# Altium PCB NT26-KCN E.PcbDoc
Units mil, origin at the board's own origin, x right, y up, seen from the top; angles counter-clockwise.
Board outline 1222.67 x 1229.6 mil, 4 copper layers (Top Layer, GND1, Signal Layer 1, Bottom Layer), stack 29.559 mil thick; 1 components, 0 nets, 109 pads, 0 vias.
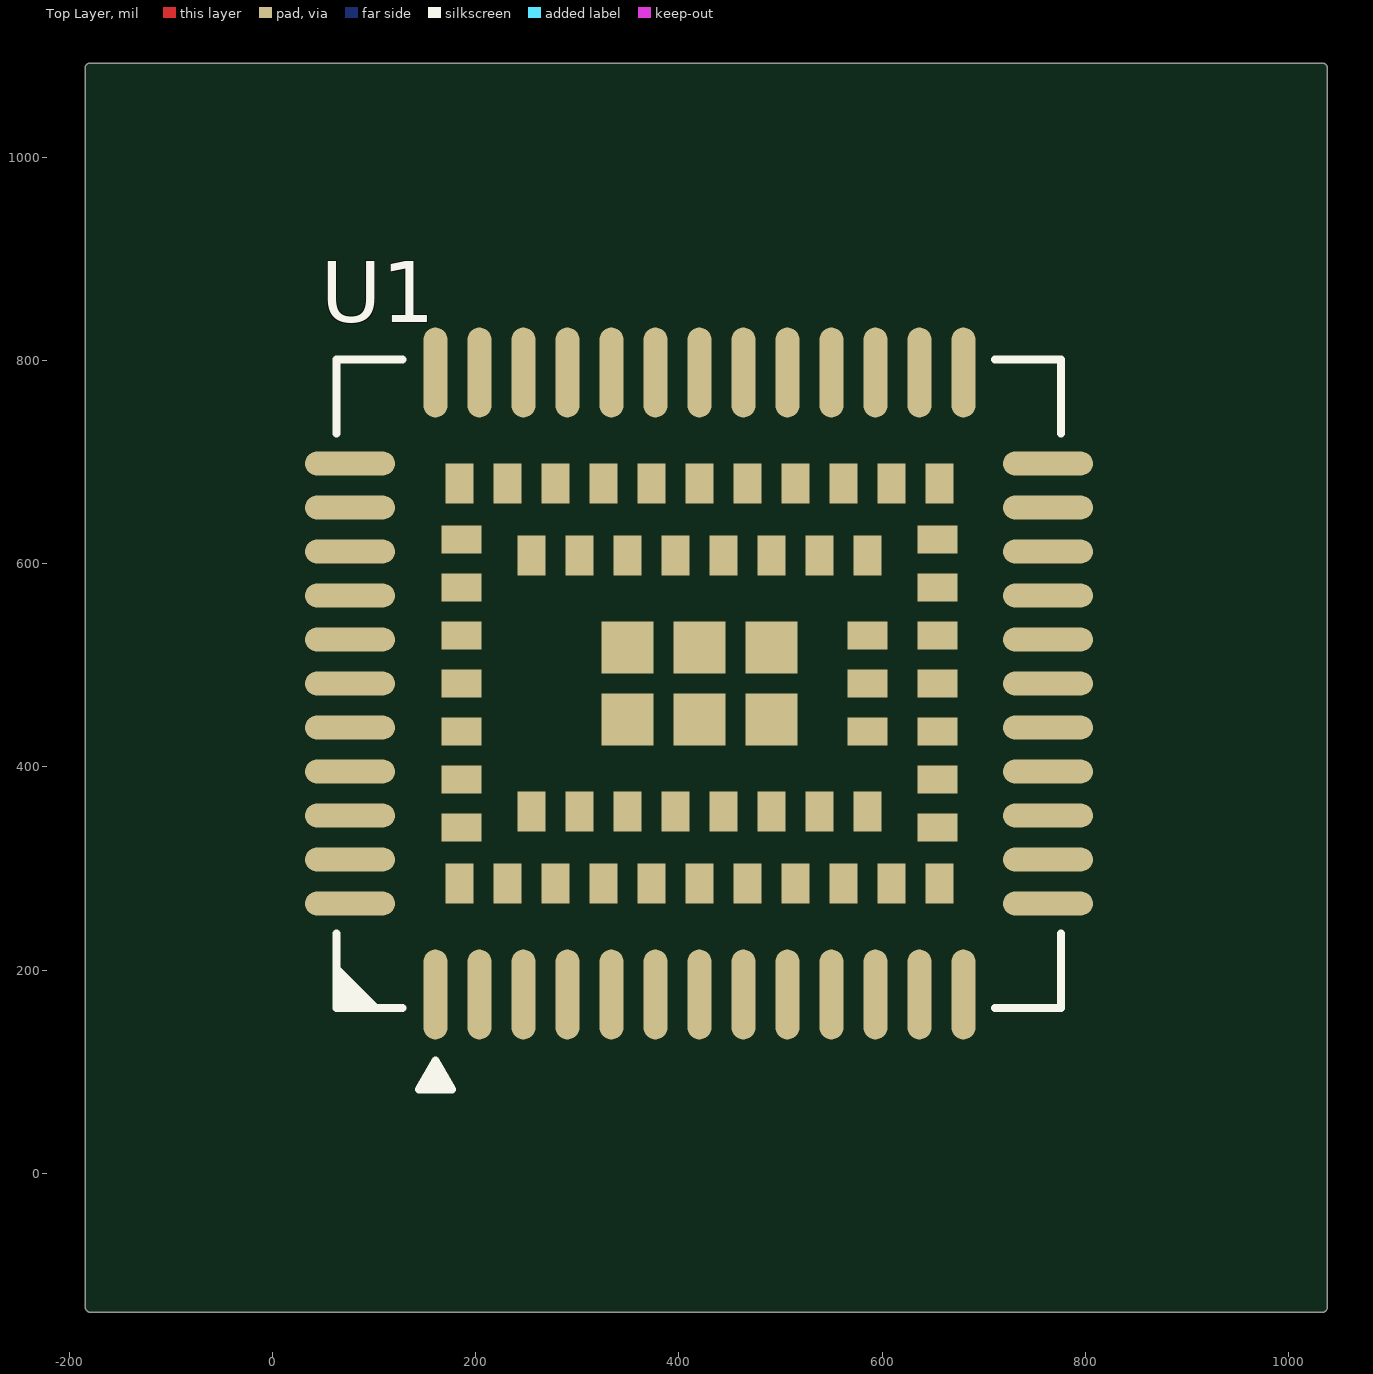
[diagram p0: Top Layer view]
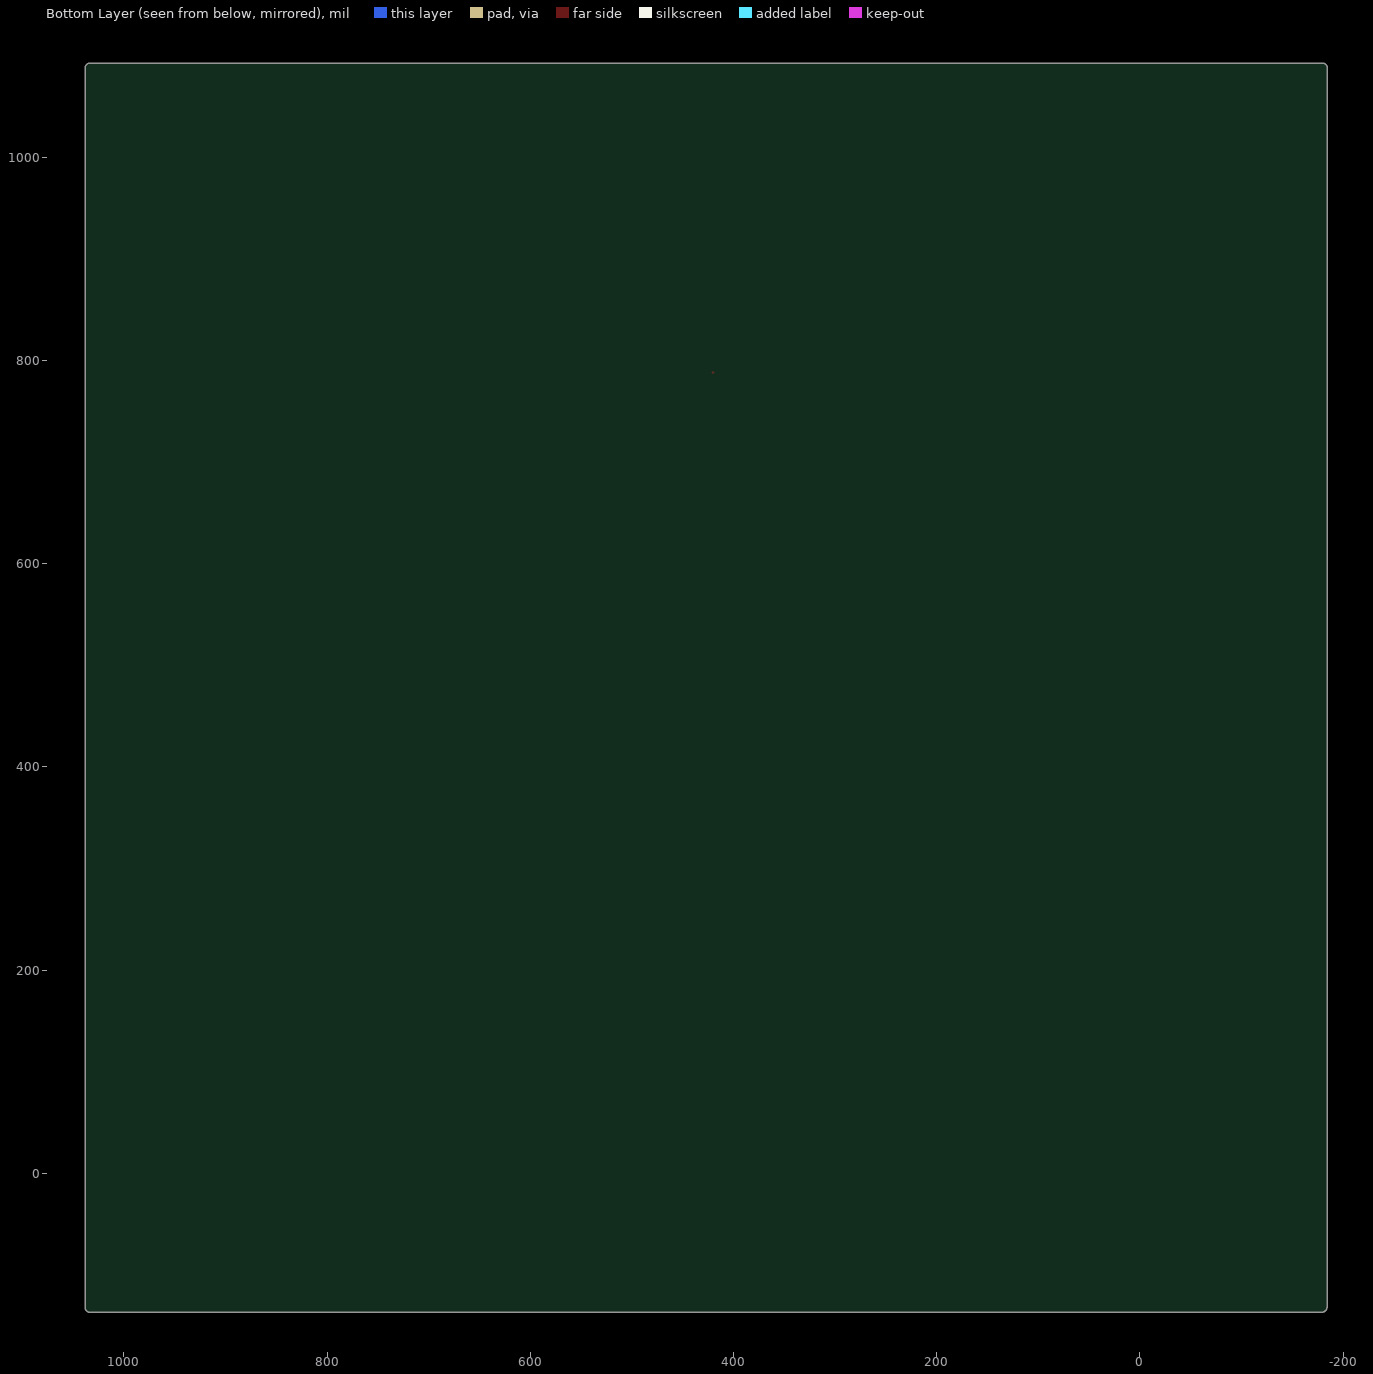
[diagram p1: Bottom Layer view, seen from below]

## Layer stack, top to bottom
Top Solder: solder mask 0.4, Solder Resist, Dk 3.5
Top Layer: signal copper 1
Dielectric1: core 2.9528, 1080, Dk 4.2
GND1: signal copper 0.9843
Dielectric2: core 19.685, 1080, Dk 4.2
Signal Layer 1: signal copper 0.9843
Dielectric 3: prepreg 2.9528, Dk 4.2
Bottom Layer: signal copper 1
Bottom Solder: solder mask 0.4, Solder Resist, Dk 3.5

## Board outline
-184.31,-131.54 -184.31,-123.37 cw(c-179.45,-122.13) -184.46,-122.13 -184.46,1087.68 cw(c-179.45,1087.68) -179.45,1092.69 1033.19,1092.69 cw(c1033.19,1087.68) 1038.2,1087.68 1038.2,-131.89 cw(c1033.19,-131.89) 1033.19,-136.9 -178.94,-136.9 cw(c-178.94,-131.89) -182.5,-135.42 -182.48,-135.44 -182.84,-135.08 -182.82,-135.1 cw(c-179.29,-131.54)

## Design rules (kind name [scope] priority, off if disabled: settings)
Clearance keepout [IsKeepOut] p1: gap=7.87 ignorepadtopadclearanceinfootprint=FALSE except(0: Arc-Arc Arc-Track Arc-SMDPad Arc-THPad Arc-Fill Arc-Poly Arc-Region Arc-Hole Track-Track Track-SMDPad Track-THPad Track-Fill Track-Poly Track-Region Track-Hole SMDPad-Hole THPad-Hole Via-Hole Fill-Hole Poly-Hole Region-Hole Text-Hole; 11.81: Arc-Via Track-Via)
Clearance Clearance_via [InDrillLayerPair('GND1 - Signal Layer 1') vs InDrillLayerPair('GND1 - Signal Layer 1')] p2: gap=5.91 ignorepadtopadclearanceinfootprint=TRUE
Clearance via [IsVia vs IsVia] p3: gap=5 ignorepadtopadclearanceinfootprint=FALSE except(4.2: Via-Via)
Clearance PAD&PAD [IsPad vs IsPad] p4: gap=7.87 ignorepadtopadclearanceinfootprint=TRUE
Clearance Clearance_50_TOP [InNetClass('Net Class_50') vs InNet('GND') And OnLayer('Top Layer')] p5: gap=3 ignorepadtopadclearanceinfootprint=TRUE except(0: Arc-Hole Track-Hole SMDPad-Hole THPad-Hole Via-Hole Fill-Hole Poly-Hole Region-Hole Text-Hole; 4.5: Arc-Fill Arc-Poly Arc-Region Track-Fill Track-Poly Track-Region SMDPad-Fill SMDPad-Poly SMDPad-Region THPad-Fill THPad-Poly THPad-Region Via-Fill Via-Poly Via-Region Fill-Fill Fill-Poly Fill-Region Poly-Poly Poly-Region Region-Region; 8: SMDPad-SMDPad)
Clearance Clearance_50_SIG [InNetClass('Net Class_50') vs InNet('GND') And OnLayer('Signal Layer 1')] p6: gap=3 ignorepadtopadclearanceinfootprint=TRUE except(0: Arc-Hole Track-Hole SMDPad-Hole THPad-Hole Via-Hole Fill-Hole Poly-Hole Region-Hole Text-Hole; 5: Arc-Fill Arc-Poly Arc-Region Track-Fill Track-Poly Track-Region SMDPad-Fill SMDPad-Poly SMDPad-Region THPad-Fill THPad-Poly THPad-Region Via-Fill Via-Poly Via-Region Fill-Fill Fill-Poly Fill-Region Poly-Poly Poly-Region Region-Region; 8: SMDPad-SMDPad)
Clearance Clearance_polygon [InPolygon] p7: gap=3 ignorepadtopadclearanceinfootprint=TRUE except(0: Arc-Hole Track-Hole SMDPad-Hole THPad-Hole Via-Hole Fill-Hole Poly-Hole Region-Hole Text-Hole; 5: Arc-Fill Arc-Poly Arc-Region Track-Fill Track-Poly Track-Region SMDPad-Fill SMDPad-Poly SMDPad-Region THPad-Fill THPad-Poly THPad-Region Via-Fill Via-Poly Via-Region Fill-Fill Fill-Poly Fill-Region Poly-Poly Poly-Region Region-Region; 8: SMDPad-SMDPad)
Clearance all [All] p8: gap=3 ignorepadtopadclearanceinfootprint=TRUE except(0: Arc-Hole Track-Hole SMDPad-Hole THPad-Hole Via-Hole Fill-Hole Poly-Hole Region-Hole Text-Hole; 4: Arc-Fill Arc-Poly Arc-Region Track-Fill Track-Poly Track-Region SMDPad-Fill SMDPad-Poly SMDPad-Region THPad-Fill THPad-Poly THPad-Region Via-Fill Via-Poly Via-Region Fill-Fill Fill-Poly Fill-Region Poly-Poly Poly-Region Region-Region; 8: SMDPad-SMDPad)
ComponentClearance [All] p1: gap=0 collisioncheckmode=3 verticalgap=0 showdistances=FALSE
DiffPairsRouting [All] p1: maxlimit=5 minlimit=5 mostfreqgap=5 toplayer_minwidth=3.25 toplayer_maxwidth=3.25 toplayer_prefwidth=3.25 midlayer1_minwidth=2.52 midlayer1_maxwidth=2.52 midlayer1_prefwidth=2.52 midlayer2_minwidth=2.52 midlayer2_maxwidth=2.52 midlayer2_prefwidth=2.52 bottomlayer_minwidth=3.25 bottomlayer_maxwidth=3.25 bottomlayer_prefwidth=3.25 maxuncoupledlength=500
HoleSize [All] p1: absolutevalues=TRUE maxlimit=196.85 minlimit=0 maxpercent=80.000 minpercent=20.000
HoleToHoleClearance [All] p1: gap=3 allowstackedmicrovias=TRUE
MinimumSolderMaskSliver [All] p1: minsoldermaskwidth=0
PolygonConnect [All] p1: connectstyle=Direct reliefconductorwidth=10 reliefentries=4 polygonreliefangle="90 Angle" airgapwidth=10
RoomDefinition "NT26-KCN E" [InComponentClass('NT26-KCN E')] p1: confinementstyle=ConfineIn formatcopy=TRUE lockcomponents=FALSE outline -12979.66,-8447.64 -10979.66,-8447.64 -10979.66,-7447.64 -12979.66,-7447.64
RoutingVias RoutingVias_1 [InDrillLayerPair('Top Layer - GND1')   OR InDrillLayerPair('Signal Layer 1 - Bottom Layer')] p1: holewidth=3.94 width=8.66 viastyle="Through Hole" minholewidth=3.94 minwidth=8.66 maxholewidth=11.81 maxwidth=19.68
RoutingVias [InDrillLayerPair('GND1 - Signal Layer 1')] p2: holewidth=7.87 width=13.78 viastyle="Through Hole" minholewidth=7.87 minwidth=13.78 maxholewidth=8.66 maxwidth=15.75
SilkToSilkClearance [All] p1: silktosilkclearance=0
SilkToSolderMaskClearance [IsPad] p1: minsilkscreentomaskgap=0 clearancetoexposedcopper=TRUE
SolderMaskExpansion [All] p1: expansion=4
Width 50 [InNetClass('Net Class_50')] p1: maxlimit=3.5 minlimit=3 preferedwidth=3.5 toplayer_minwidth=3.5 midlayer1_maxwidth=3 midlayer1_prefwidth=3 midlayer2_maxwidth=3 midlayer2_prefwidth=3 bottomlayer_minwidth=3.5 minimp=50.000000 maximp=50.000000 favimp=50.000000
Width [All] p2: maxlimit=196.85 minlimit=2.76 preferedwidth=2.99
23 further rules are at their usual default settings.

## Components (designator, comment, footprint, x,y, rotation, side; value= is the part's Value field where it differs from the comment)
U1 "NT26-KCN E" "NT26-KCN E" 420.2,481.93 r0 top

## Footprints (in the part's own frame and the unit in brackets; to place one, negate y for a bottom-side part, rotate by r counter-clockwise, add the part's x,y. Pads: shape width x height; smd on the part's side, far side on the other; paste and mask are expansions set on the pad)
"NT26-KCN E" [mm]
  oval 0.6x2.25 smd mask+0.102: 1(-6.6,-7.775) 2(-5.5,-7.775) 3(-4.4,-7.775) 4(-3.3,-7.775) 5(-2.2,-7.775) 6(-1.1,-7.775) 7(0,-7.775) 8(1.1,-7.775) 9(2.2,-7.775) 10(3.3,-7.775) 11(4.4,-7.775) 12(5.5,-7.775) 13(6.6,-7.775) 23(6.6,7.775) 24(5.5,7.775) 25(4.4,7.775) 26(3.3,7.775) 27(2.2,7.775) 28(1.1,7.775) 29(0,7.775) 30(-1.1,7.775) 31(-2.2,7.775) 32(-3.3,7.775) 33(-4.4,7.775) 34(-5.5,7.775) 35(-6.6,7.775)
  oval 2.25x0.6 smd mask+0.102: 14(8.714,-4.4) 15(8.714,-3.3) 16(8.714,-2.2) 17(8.714,-1.1) 18(8.714,0) 19(8.714,1.1) 20(8.714,2.2) 21(8.714,3.3) 22(8.714,4.4) 36(-8.736,4.4) 37(-8.736,3.3) 38(-8.736,2.2) 39(-8.736,1.1) 40(-8.736,0) 41(-8.736,-1.1) 42(-8.736,-2.2) 43(-8.736,-3.3) 44(-8.736,-4.4) 95(8.714,-5.5) 96(8.714,5.5) 97(-8.736,5.5) 98(-8.736,-5.5)
  rect 0.7x1 smd: 45(-4.8,-5) 46(-3.6,-5) 47(-2.4,-5) 48(-1.2,-5) 49(0,-5) 50(1.2,-5.003) 51(2.4,-5.003) 52(3.6,-5.003) 53(4.8,-5.003) 59(4.8,5) 60(3.6,5) 61(2.4,5) 62(1.2,5) 63(0,5) 64(-1.2,5) 65(-2.4,5) 66(-3.6,5) 67(-4.8,5) 73(-4.2,-3.2) 74(-3,-3.2) 75(-1.8,-3.2) 76(-0.6,-3.2) 77(0.6,-3.2) 78(1.8,-3.2) 79(3,-3.2) 80(4.2,-3.2) 81(4.2,3.2) 82(3,3.2) 83(1.8,3.2) 84(0.6,3.2) 85(-0.6,3.2) 86(-1.8,3.2) 87(-3,3.2) 88(-4.2,3.2) 99(-6,-5) 100(6,-5) 103(6,5) 104(-6,5)
  rect 1x0.7 smd: 54(5.95,-2.4) 55(5.95,-1.2) 56(5.95,0) 57(5.95,1.2) 58(5.95,2.4) 68(-5.95,2.4) 69(-5.95,1.2) 70(-5.95,0) 71(-5.95,-1.2) 72(-5.95,-2.4) 101(5.95,-3.6) 102(5.95,3.6) 105(-5.95,3.6) 106(-5.95,-3.6) 107(4.2,-1.2) 108(4.2,0) 109(4.2,1.2)
  rect 1.3x1.3 smd: 89(-1.8,-0.9) 90(0,-0.9) 91(1.8,-0.9) 92(1.8,0.9) 93(0,0.9) 94(-1.8,0.9)
  Top Layer lines w0.076: 0,7.775 0,7.775
  silkscreen extent -9.07,-10.14 9.05,8.11

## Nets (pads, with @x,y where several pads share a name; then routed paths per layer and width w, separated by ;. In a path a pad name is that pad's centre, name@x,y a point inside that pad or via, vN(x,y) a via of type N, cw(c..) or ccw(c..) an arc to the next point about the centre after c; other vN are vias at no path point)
pads on no net: U1.1 U1.2 U1.3 U1.4 U1.5 U1.6 U1.7 U1.8 U1.9 U1.10 U1.11 U1.12 U1.13 U1.14 U1.15 U1.16 U1.17 U1.18 U1.19 U1.20 U1.21 U1.22 U1.23 U1.24 U1.25 U1.26 U1.27 U1.28 U1.29 U1.30 U1.31 U1.32 U1.33 U1.34 U1.35 U1.36 U1.37 U1.38 U1.39 U1.40 U1.41 U1.42 U1.43 U1.44 U1.45 U1.46 U1.47 U1.48 U1.49 U1.50 U1.51 U1.52 U1.53 U1.54 U1.55 U1.56 U1.57 U1.58 U1.59 U1.60 U1.61 U1.62 U1.63 U1.64 U1.65 U1.66 U1.67 U1.68 U1.69 U1.70 U1.71 U1.72 U1.73 U1.74 U1.75 U1.76 U1.77 U1.78 U1.79 U1.80 U1.81 U1.82 U1.83 U1.84 U1.85 U1.86 U1.87 U1.88 U1.89 U1.90 U1.91 U1.92 U1.93 U1.94 U1.95 U1.96 U1.97 U1.98 U1.99 U1.100 U1.101 U1.102 U1.103 U1.104 U1.105 U1.106 U1.107 U1.108 U1.109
